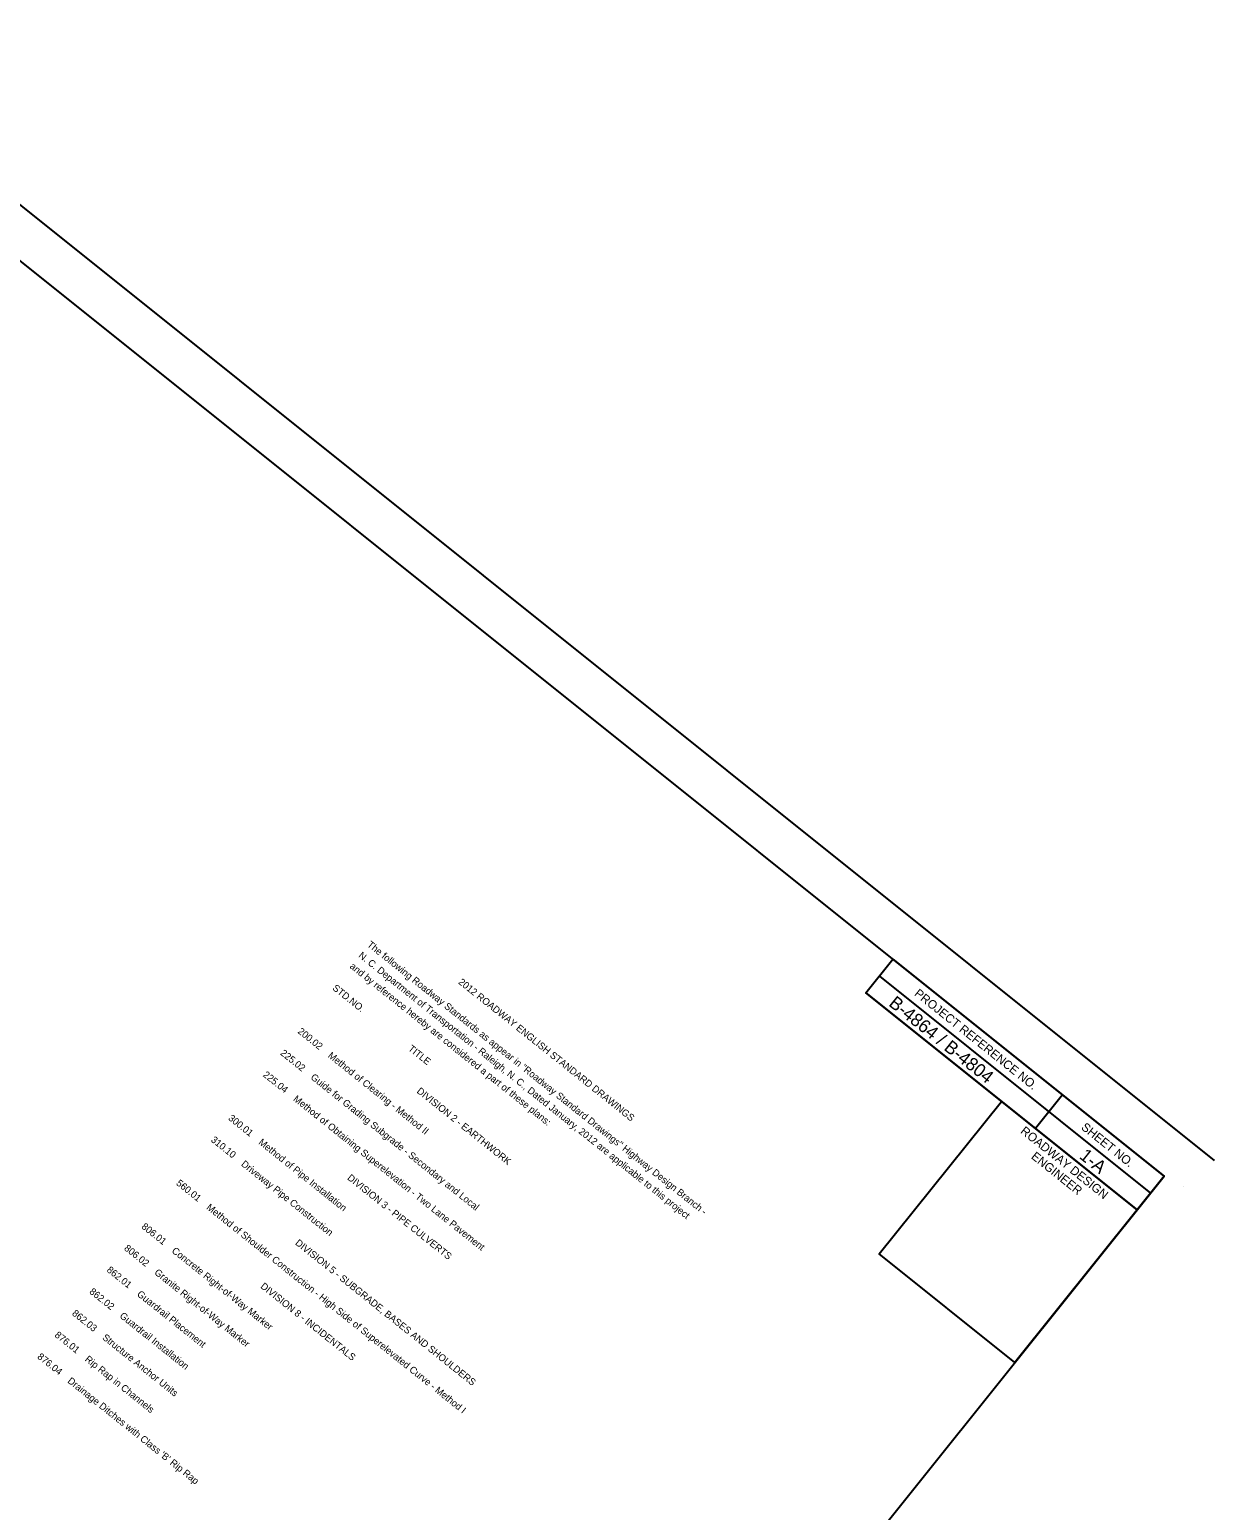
# Model space of a CAD drawing. Extents: x 1730256 to 1738218, y 910410 to 917906.
# Drawn here: x 1731576 to 1732259, y 911068 to 911921 of the extents above; entities that cross this region are included whole.
import ezdxf

# ---------------------------------------------------------------- set-up
doc = ezdxf.new("R2010")
doc.units = 0
for name, color, linetype in [('Old_Level_1', 7, 'Continuous'), ('Old_Level_18', 7, 'Continuous'), ('Old_Level_40', 7, 'Continuous'), ('Old_Level_44', 7, 'Continuous'), ('Old_Level_50', 7, 'Continuous'), ('Old_Level_51', 7, 'Continuous'), ('Old_Level_52', 7, 'Continuous')]:
    doc.layers.add(name, color=color, linetype=linetype)

msp = doc.modelspace()

# ---------------------------------------------------------------- linework, layer by layer
at = {"layer": 'Old_Level_1'}
msp.add_line((1732241.06, 911254.42), (1732241.06, 911254.42), dxfattribs=at)
at = {"layer": 'Old_Level_18'}
msp.add_lwpolyline([(1732229.7, 911260.24), (1731058.58, 912197.51), (1730402.49, 911377.72), (1731573.62, 910440.45)], close=True, dxfattribs=at)
at = {"layer": 'Old_Level_40'}
for p, q in [((1732065.67, 911375.44), (1732221.86, 911250.44)), ((1732057.86, 911365.68), (1732214.05, 911240.68)), ((1732171.12, 911307.06), (1732155.5, 911287.54)), ((1732214.05, 911240.68), (1732143.79, 911152.89))]:
    msp.add_line(p, q, dxfattribs=at)
for points in [[(1732073.51, 911385.24), (1732229.7, 911260.24), (1732214.05, 911240.68), (1732057.86, 911365.68)], [(1732135.94, 911303.2), (1732214.05, 911240.68), (1732143.76, 911152.85), (1732065.64, 911215.36)]]:
    msp.add_lwpolyline(points, close=True, dxfattribs=at)
at = {"layer": 'Old_Level_50'}
msp.add_line((1732258.6, 911269.14), (1732258.6, 911269.14), dxfattribs=at)
at = {"layer": 'Old_Level_51'}
msp.add_line((1732258.6, 911269.14), (1730943.82, 912321.37), dxfattribs=at)
at = {"layer": 'Old_Level_52'}
msp.add_line((1732241.06, 911254.42), (1732241.06, 911254.42), dxfattribs=at)

# ---------------------------------------------------------------- texts
at = {"layer": 'Old_Level_1'}
for s, p in [('The following Roadway Standards as appear in "Roadway Standard Drawings" Highway Design Branch -', (1731770.34, 911392.88)), ('N. C. Department of Transportation - Raleigh, N. C., Dated January, 2012 are applicable to this project', (1731765.35, 911386.63)), ('and by reference hereby are considered a part of these plans:', (1731760.35, 911380.39)), ('STD.NO.                       TITLE', (1731750.35, 911367.89)), ('2012 ROADWAY ENGLISH STANDARD DRAWINGS', (1731822.88, 911371.33)), ('200.02    Method of Clearing - Method II', (1731730.35, 911342.91)), ('225.02    Guide for Grading Subgrade - Secondary and Local', (1731720.36, 911330.42)), ('225.04    Method of Obtaining Superelevation - Two Lane Pavement', (1731710.36, 911317.93)), ('DIVISION 2 - EARTHWORK', (1731798.91, 911308.54)), ('300.01    Method of Pipe Installation ', (1731690.36, 911292.94)), ('310.10    Driveway Pipe Construction', (1731680.37, 911280.45)), ('DIVISION 3 - PIPE CULVERTS', (1731758.92, 911258.57)), ('560.01    Method of Shoulder Construction - High Side of Superelevated Curve - Method I', (1731660.37, 911255.47)), ('806.01    Concrete Right-of-Way Marker', (1731640.38, 911230.48)), ('806.02    Granite Right-of-Way Marker', (1731630.38, 911217.99)), ('DIVISION 5 - SUBGRADE, BASES AND SHOULDERS', (1731728.93, 911221.09)), ('862.01    Guardrail Placement', (1731620.38, 911205.5)), ('862.02    Guardrail Installation', (1731610.38, 911193.01)), ('DIVISION 8 - INCIDENTALS', (1731708.93, 911196.11)), ('862.03    Structure Anchor Units', (1731600.39, 911180.51)), ('876.01    Rip Rap in Channels', (1731590.39, 911168.02)), ("876.04    Drainage Ditches with Class 'B' Rip Rap", (1731580.39, 911155.53))]:
    msp.add_text(s, height=3.9999, rotation=321.32968, dxfattribs=at).set_placement(p)
at = {"layer": 'Old_Level_44'}
for s, height, p in [('B-4864 / B-4804', 7.5, (1732070.57, 911358.71)), ('PROJECT REFERENCE NO.', 5.0001, (1732085.41, 911364.58)), ('ROADWAY DESIGN', 5.0001, (1732146.52, 911285.38)), ('SHEET NO.', 5, (1732181.5, 911287.55)), ('ENGINEER', 5, (1732152.7, 911270.76)), ('1-A', 7.5, (1732180.34, 911270.86))]:
    msp.add_text(s, height=height, rotation=321.32919, dxfattribs=at).set_placement(p)

doc.saveas('drawing.dxf')
